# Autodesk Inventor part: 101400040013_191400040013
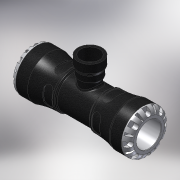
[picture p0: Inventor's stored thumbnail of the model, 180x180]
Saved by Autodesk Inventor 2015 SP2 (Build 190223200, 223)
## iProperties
Created: 2016-12
Part Number: 101400040013_191400040013
Material: PVC-Piping
Description: PLASSON TEE WITH THREADED FEMALE OFFTAKE 40X1 1/4" SERIES 1
Document SubType Name: Modeling
Designer: KIM
Mass: 524.398 g
Surface Area: 829.136 cm^2
Volume: 374.57 cm^3
Density: 1.4 g/cm^3
Appearance: Black Cast
Author: KIM
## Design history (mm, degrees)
derived "1014.ipt"
feature "Solid1::1014.ipt"
tag "TaggingFeature1"
body "Solid1"
other parameters: "d1" = 29.4, "d8" = 59.5, "d13" = 8, "d14" = 8, "d15" = 0, "d17" = 360 deg, "d19" = 8 deg, "d20" = 0.8, "d21" = 0.8, "d22" = 8 deg, "d24" = 0, "d26" = 360 deg, "d33" = 7, "d43" = 54.6, "d51" = 0.7, "d54" = 14, "d55" = 8.8, "d57" = 15.68, "d58" = 0, "d74" = 0, "d77" = 3.33333, "d79" = 54.6, "d80" = 192, "d82" = 0.8, "d115" = 360 deg, "d139" = 8, "d140" = 0, "d142" = 360 deg, "d207" = 90 deg, "d228" = 11.9, "d247" = 1.4, "d248" = 4.2, "d266" = 0, "d268" = 38.952, "d270" = 5.8428, "d271" = 8, "d274" = 2.9214, "d275" = 73, "d276" = 3.8952, "d277" = 3.8952, "d278" = 3.8952, "d279" = 3.8952, "d281" = 0, "d282" = 24, "A_" = 73, "H_" = 192, "Rp_" = 38.952, "l_2" = 24, "d9" = 10
